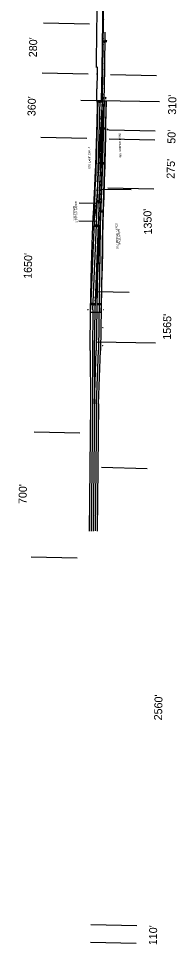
# Model space of a CAD drawing. Extents: x 1651568 to 1653044, y 601329 to 611807.
# Drawn here: x 1652071 to 1652957, y 601329 to 606513 of the extents above; entities that cross this region are included whole.
import ezdxf

# ---------------------------------------------------------------- set-up
doc = ezdxf.new("R2010")
doc.units = 0
for name, color, linetype in [('CM_Corridor_Design', 7, 'Continuous'), ('Default', 7, 'Continuous'), ('DR_X_Storm_Sewer', 7, 'Continuous'), ('DT_X_Break_Line', 7, 'Continuous'), ('DT_X_Contour_Major', 7, 'Continuous'), ('DT_X_Void', 7, 'Continuous'), ('GE_P_Alignment_500_Cardinal_Points', 7, 'Continuous'), ('GE_P_Alignment_500_Distances', 7, 'Continuous'), ('MD_P_Intersection_MatchLine', 7, 'Continuous'), ('PF_P_Grade_Line', 7, 'Continuous'), ('PF_P_Grade_Line_LT', 7, 'Continuous'), ('PF_X_Ground_Line', 7, 'Continuous'), ('PF_X_Ground_Line_LT', 7, 'Continuous'), ('PF_X_Ground_Line_RT', 7, 'Continuous'), ('PV_P_EOP', 7, 'Continuous'), ('PV_X_EOP', 7, 'Continuous'), ('RW_X_Esmt_LA', 7, 'Continuous'), ('SC_Scratch3', 7, 'Continuous')]:
    doc.layers.add(name, color=color, linetype=linetype)

msp = doc.modelspace()

# ---------------------------------------------------------------- linework, layer by layer
at = {"layer": 'CM_Corridor_Design'}
for p, q in [((1652550.1, 606379.2), (1652548.4, 606382.6)), ((1652550.1, 606379.2), (1652550.3, 606391.1)), ((1652550.1, 606379.2), (1652551.9, 606382.6)), ((1652562.4, 606391.9), (1652560.6, 606388.5)), ((1652562.4, 606391.9), (1652562.3, 606380)), ((1652562.4, 606391.9), (1652564.1, 606388.5)), ((1652545.6, 606061.3), (1652544, 606064.7)), ((1652545.6, 606061.3), (1652545.8, 606073.2)), ((1652545.6, 606061.3), (1652547.4, 606064.7)), ((1652558.4, 606073.2), (1652556.6, 606069.8)), ((1652558.4, 606073.2), (1652558.2, 606061.3)), ((1652558.4, 606073.2), (1652560, 606069.8)), ((1652537.6, 605892.1), (1652536, 605895.6)), ((1652537.6, 605892.1), (1652538.2, 605904)), ((1652537.6, 605892.1), (1652539.5, 605895.4)), ((1652552.2, 605903.6), (1652550.5, 605900.2)), ((1652552.2, 605903.6), (1652552.1, 605891.7)), ((1652552.2, 605903.6), (1652553.9, 605900.2)), ((1652527.9, 605697.6), (1652526.3, 605701.1)), ((1652527.9, 605697.6), (1652528.4, 605709.5)), ((1652527.9, 605697.6), (1652529.7, 605700.9)), ((1652546.1, 605708.3), (1652544.3, 605704.9)), ((1652546.1, 605708.3), (1652545.9, 605696.4)), ((1652546.1, 605708.3), (1652547.8, 605704.9)), ((1652516.5, 605484.2), (1652515, 605487.6)), ((1652516.5, 605484.2), (1652517.1, 605496)), ((1652516.5, 605484.2), (1652518.4, 605487.4)), ((1652537.5, 605438.6), (1652535.8, 605435.2)), ((1652537.5, 605438.6), (1652537.4, 605426.7)), ((1652537.5, 605438.6), (1652539.2, 605435.2)), ((1652500.3, 605347.7), (1652498.7, 605351.2)), ((1652500.3, 605347.7), (1652500.8, 605359.6)), ((1652500.3, 605347.7), (1652502.1, 605351)), ((1652512.1, 605347.4), (1652510.5, 605350.9)), ((1652512.1, 605347.4), (1652512.7, 605359.3)), ((1652512.1, 605347.4), (1652514, 605350.7)), ((1652482.4, 604908.8), (1652480.8, 604912.2)), ((1652482.4, 604908.8), (1652483, 604920.6)), ((1652482.4, 604908.8), (1652484.3, 604912)), ((1652494.2, 604908.5), (1652492.7, 604911.9)), ((1652494.2, 604908.5), (1652494.8, 604920.3)), ((1652494.2, 604908.5), (1652496.1, 604911.8)), ((1652516.1, 604919.9), (1652514.4, 604916.6)), ((1652516.1, 604919.9), (1652516, 604908.1)), ((1652516.1, 604919.9), (1652517.8, 604916.5)), ((1652529.3, 604919.6), (1652527.5, 604916.3)), ((1652529.3, 604919.6), (1652529.2, 604907.8)), ((1652529.3, 604919.6), (1652531, 604916.2))]:
    msp.add_line(p, q, dxfattribs=at)
at = {"layer": 'Default'}
msp.add_lwpolyline([(1652561.2, 606051.4), (1652560.5, 605997.6), (1652559.3, 605931.6), (1652557.9, 605851.7), (1652556.6, 605787.9), (1652554.4, 605691), (1652551.8, 605605.9), (1652548.6, 605514.1), (1652546.2, 605440.2), (1652544.1, 605364.6), (1652542.4, 605296.2), (1652540.8, 605209.6), (1652539.5, 605125.1), (1652535.9, 605025.9), (1652533.7, 604920.6), (1652533, 604867.1), (1652473.9, 604867.3), (1652474, 604883.4), (1652477.2, 604953.6), (1652478.6, 605051.2), (1652480.5, 605126.3), (1652482.2, 605188.7), (1652484.4, 605251.8), (1652485.9, 605296.5), (1652488.1, 605354.7), (1652489.8, 605399), (1652492.5, 605450.4), (1652495.1, 605500.8), (1652498.7, 605571.5), (1652501.1, 605625.4), (1652503.6, 605690.8), (1652506, 605754), (1652508, 605815.7), (1652509.8, 605869.3), (1652511.8, 605944.5), (1652513.2, 606013), (1652513.7, 606052.2)], close=True, dxfattribs=at)
at = {"layer": 'DR_X_Storm_Sewer'}
msp.add_lwpolyline([(1652536.1, 605556.8), (1652529.3, 605358.1), (1652526.8, 605192.9), (1652523.5, 604981.8)], dxfattribs=at)
at = {"layer": 'DT_X_Break_Line'}
for centre, radius in [((1652545.5, 606471.7), 1), ((1652546, 606506.7), 1), ((1652545.1, 606436.7), 1), ((1652544.3, 606366.7), 1), ((1652544.7, 606401.7), 1), ((1652543.8, 606331.7), 1), ((1652543, 606261.7), 1), ((1652543.4, 606296.7), 1), ((1652542.6, 606226.7), 1), ((1652541.4, 606156.7), 1), ((1652542, 606191.7), 1), ((1652540.8, 606121.7), 1), ((1652539.6, 606051.7), 1), ((1652540.2, 606086.7), 1), ((1652536.9, 606001.8), 1), ((1652533.2, 605951.8), 2), ((1652530.5, 605901.9), 2), ((1652545, 605901.5), 2), ((1652527.8, 605851.9), 2), ((1652542.8, 605851.6), 2), ((1652525.1, 605801.9), 2), ((1652540.9, 605801.6), 2), ((1652522.4, 605752), 2), ((1652538.8, 605751.6), 2), ((1652519.7, 605702), 2), ((1652535.3, 605701.7), 2), ((1652538.3, 605701.6), 2), ((1652517, 605652.1), 2), ((1652532.9, 605651.7), 2), ((1652536.7, 605651.6), 2), ((1652514.3, 605602.1), 2), ((1652530.5, 605601.7), 2), ((1652535, 605601.6), 2), ((1652511.6, 605552.1), 2), ((1652528, 605551.8), 2), ((1652533.6, 605551.6), 2), ((1652507.5, 605478.1), 2), ((1652508.9, 605502.2), 2), ((1652525.5, 605501.8), 2), ((1652531.4, 605501.7), 2), ((1652502.2, 605442.7), 2), ((1652505.2, 605462.4), 2), ((1652529.3, 605451.7), 2), ((1652495.9, 605403.2), 2), ((1652499.1, 605423), 2), ((1652527.2, 605401.7), 2), ((1652525.1, 605351.7), 2), ((1652523.1, 605301.8), 2), ((1652521, 605251.8), 2), ((1652518.9, 605201.8), 2), ((1652516.8, 605151.9), 2), ((1652514.7, 605101.9), 2), ((1652512.7, 605051.9), 2), ((1652506.8, 604969), 2), ((1652510.1, 604983.6), 2), ((1652510.6, 605001.9), 2), ((1652502.9, 604952.8), 2)]:
    msp.add_circle(centre, radius, dxfattribs=at)
at = {"layer": 'DT_X_Contour_Major'}
for p, q in [((1652540, 606229.1), (1652551.8, 607199.3)), ((1652507.5, 606238.7), (1652510.6, 606459.9)), ((1652514.1, 606240.6), (1652507.5, 606238.7)), ((1652513.5, 606206.6), (1652514.1, 606240.6)), ((1652513.5, 606197.5), (1652513.5, 606206.6)), ((1652537, 606051.8), (1652540, 606229.1)), ((1652509.9, 606079.3), (1652510.5, 606120.3)), ((1652510.5, 606120.3), (1652512.5, 606121.2)), ((1652509.5, 606053.1), (1652509.9, 606079.3)), ((1652509.5, 606052.3), (1652509.5, 606053.1)), ((1652513.7, 606052.2), (1652537, 606051.8))]:
    msp.add_line(p, q, dxfattribs=at)
for points in [[(1652551.8, 607199.3), (1652540, 606229.1), (1652537, 606051.8), (1652509.5, 606052.3), (1652509.9, 606079.3), (1652510.5, 606120.3), (1652512.5, 606121.2), (1652512.7, 606131.8), (1652513.5, 606197.5), (1652513.5, 606206.6), (1652514.1, 606240.6), (1652507.5, 606238.7), (1652510.6, 606459.8), (1652510.6, 606459.9), (1652511.3, 606521.8)], [(1652551.8, 607199.3), (1652540, 606229.1), (1652537, 606051.8), (1652509.5, 606052.3), (1652509.9, 606079.3), (1652510.5, 606120.3), (1652512.5, 606121.2), (1652512.7, 606131.8), (1652513.5, 606197.5), (1652513.5, 606206.6), (1652514.1, 606240.6), (1652507.5, 606238.7), (1652510.6, 606459.8), (1652510.6, 606459.9), (1652511.3, 606521.8)], [(1652510.6, 606459.8), (1652511.3, 606521.8), (1652511.5, 606531.9), (1652513, 606640.4), (1652508.6, 606640.4), (1652508.7, 606654.8), (1652513.2, 606654.8), (1652514.1, 606733)], [(1652512.5, 606121.2), (1652512.7, 606131.8), (1652513.5, 606197.5)]]:
    msp.add_lwpolyline(points, dxfattribs=at)
at = {"layer": 'DT_X_Void'}
for p, q in [((1652511.3, 606046.6), (1652521.3, 606046.5)), ((1652511.4, 606048.6), (1652521.4, 606048.5)), ((1652518.3, 606045), (1652514.3, 606045)), ((1652515.3, 606046.5), (1652515.3, 606045)), ((1652516.4, 606047.5), (1652516.4, 606047.5)), ((1652517.3, 606046.5), (1652517.3, 606045)), ((1652524.2, 606048.5), (1652534.2, 606048.4)), ((1652524.2, 606046.5), (1652534.2, 606046.4)), ((1652531.2, 606044.9), (1652527.2, 606045)), ((1652528.2, 606046.5), (1652528.2, 606045)), ((1652529.2, 606047.4), (1652529.2, 606047.4)), ((1652530.2, 606046.4), (1652530.2, 606044.9))]:
    msp.add_line(p, q, dxfattribs=at)
for points in [[(1652510.4, 606050.6), (1652510.3, 606044.6), (1652511.3, 606044.6), (1652511.4, 606050.6)], [(1652522.4, 606050.4), (1652522.3, 606044.4), (1652521.3, 606044.5), (1652521.4, 606050.5)], [(1652523.3, 606050.5), (1652523.2, 606044.5), (1652524.2, 606044.5), (1652524.3, 606050.5)], [(1652535.3, 606050.4), (1652535.2, 606044.4), (1652534.2, 606044.4), (1652534.3, 606050.4)]]:
    msp.add_lwpolyline(points, close=True, dxfattribs=at)
at = {"layer": 'GE_P_Alignment_500_Cardinal_Points'}
for p, q in [((1652468.2, 606481.1), (1652210.8, 606487.1)), ((1652461.8, 606201.2), (1652204.3, 606207.2)), ((1652861.9, 606046.2), (1652421, 606053.8)), ((1652453.4, 605841.3), (1652195.9, 605847.3)), ((1652701.6, 605553.9), (1652536.1, 605556.8)), ((1652511.4, 605477.1), (1652411.2, 605478.9)), ((1652509.7, 605377.2), (1652409.5, 605378.9)), ((1652838.7, 604696.3), (1652507.8, 604702))]:
    msp.add_line(p, q, dxfattribs=at)
at = {"layer": 'GE_P_Alignment_500_Distances'}
msp.add_line((1652691.7, 604979), (1652512.3, 604982.1), dxfattribs=at)
at = {"layer": 'MD_P_Intersection_MatchLine'}
for p, q in [((1652510.8, 606204.9), (1652512, 606204.9)), ((1652511.2, 606206.1), (1652512, 606206.1))]:
    msp.add_line(p, q, dxfattribs=at)
msp.add_lwpolyline([(1652511.2, 606206.1), (1652509.6, 606200.1), (1652512, 606200.1)], dxfattribs=at)
msp.add_circle((1652510.3, 606202.9), 1.3, dxfattribs=at)
msp.add_arc((1652512, 606205.5), 0.638, 268.8767, 91.1233, dxfattribs=at)
at = {"layer": 'PF_P_Grade_Line'}
for p, q in [((1652515.5, 606052.6), (1652502, 605598.4)), ((1652562.5, 606051.2), (1652549, 605597)), ((1652549, 605597), (1652540.8, 605357.7)), ((1652494.1, 605377.4), (1652474, 604883.4)), ((1652540.8, 605357.7), (1652530, 604655.4)), ((1652473.4, 604654.8), (1652474, 604883.4)), ((1652473.4, 604654.8), (1652474.9, 604355.7)), ((1652519.9, 604356.4), (1652530, 604655.4)), ((1652474.9, 604355.7), (1652467.1, 603643.1)), ((1652519.9, 604356.4), (1652512.1, 603643.8))]:
    msp.add_line(p, q, dxfattribs=at)
msp.add_lwpolyline([(1652494.1, 605377.4), (1652502, 605598.4), (1652515.5, 606052.6)], dxfattribs=at)
at = {"layer": 'PF_P_Grade_Line_LT'}
for p, q in [((1652568.6, 605891.9), (1652568.7, 605892.8)), ((1652568.6, 605891.9), (1652574.6, 605890.2)), ((1652569.9, 605891.5), (1652569.9, 605892.7))]:
    msp.add_line(p, q, dxfattribs=at)
msp.add_circle((1652571.8, 605891), 1.3, dxfattribs=at)
msp.add_arc((1652569.3, 605892.8), 0.638, 357.894, 180.1406, dxfattribs=at)
at = {"layer": 'PF_X_Ground_Line'}
for p, q in [((1652562.8, 605925), (1652559.6, 605925)), ((1652561.2, 605925), (1652561.3, 605926.6)), ((1652561.2, 605925), (1652561.2, 605925)), ((1652458.5, 604883.5), (1652461.7, 604883.4)), ((1652460.1, 604883.5), (1652460, 604881.9)), ((1652460.1, 604883.5), (1652460.1, 604883.5)), ((1652547.7, 604881.4), (1652544.5, 604881.5)), ((1652546.1, 604881.5), (1652546.1, 604883.1)), ((1652546.1, 604881.5), (1652546.1, 604881.5)), ((1652546, 604781.5), (1652542.8, 604781.5)), ((1652544.4, 604781.5), (1652544.4, 604783.1)), ((1652544.4, 604781.5), (1652544.4, 604781.5)), ((1652544.3, 604681.5), (1652541.1, 604681.5)), ((1652542.7, 604681.5), (1652542.7, 604683.1)), ((1652542.7, 604681.5), (1652542.7, 604681.5))]:
    msp.add_line(p, q, dxfattribs=at)
at = {"layer": 'PF_X_Ground_Line_LT'}
for p, q in [((1652539.5, 606051.9), (1652526, 605597.7)), ((1652526, 605597.7), (1652517.8, 605358.4)), ((1652517.3, 605358.4), (1652497.9, 604882.4)), ((1652518.3, 605358.4), (1652507, 604654.3)), ((1652497.9, 604882.4), (1652495.4, 604654.4)), ((1652495.4, 604654.4), (1652496.4, 604355.3)), ((1652497.4, 604355.3), (1652507, 604654.3)), ((1652496.9, 604355.3), (1652489.1, 603642.7))]:
    msp.add_line(p, q, dxfattribs=at)
at = {"layer": 'PF_X_Ground_Line_RT'}
for p, q in [((1652527.5, 606052.2), (1652514, 605598)), ((1652551, 606051.5), (1652537.5, 605597.3)), ((1652514, 605598.1), (1652505.8, 605358.8)), ((1652537.5, 605597.3), (1652529.3, 605358.1)), ((1652505.3, 605358.9), (1652485.9, 604882.9)), ((1652529.3, 605358.1), (1652518.5, 604655.6)), ((1652487.4, 604882.7), (1652484.9, 604654.5)), ((1652484.9, 604654.5), (1652486.4, 604355.4)), ((1652508.4, 604356.6), (1652518.5, 604655.6)), ((1652486.4, 604355.4), (1652478.6, 603642.8)), ((1652508.4, 604356.6), (1652500.6, 603644))]:
    msp.add_line(p, q, dxfattribs=at)
at = {"layer": 'PV_P_EOP'}
for p, q in [((1652544, 606229), (1652555.8, 607199.3)), ((1652541, 606051.7), (1652544, 606229)), ((1652509.9, 605477.1), (1652541, 606051.7)), ((1652494.3, 605377.4), (1652509.9, 605477.1))]:
    msp.add_line(p, q, dxfattribs=at)
at = {"layer": 'PV_X_EOP'}
for p, q in [((1652554, 606228.9), (1652556.5, 606437.4)), ((1652551, 606051.5), (1652554, 606228.8))]:
    msp.add_line(p, q, dxfattribs=at)
at = {"layer": 'RW_X_Esmt_LA'}
for p, q in [((1652521.9, 605476.9), (1652550.5, 606051.6)), ((1652536.1, 605556.8), (1652551.5, 606051.5)), ((1652512.3, 604982.1), (1652536.1, 605556.8)), ((1652500, 604932.5), (1652512.3, 604982.1))]:
    msp.add_line(p, q, dxfattribs=at)
at = {"layer": 'SC_Scratch3'}
for p, q in [((1652844, 606192.3), (1652586.6, 606198.3)), ((1652836.8, 605882.4), (1652579.4, 605888.4)), ((1652835.7, 605832.4), (1652578.2, 605838.4)), ((1652829.3, 605557.5), (1652571.8, 605563.5)), ((1652415.2, 604191.7), (1652157.7, 604197.7)), ((1652793, 603992.9), (1652535.6, 603998.9)), ((1652399, 603491.9), (1652141.5, 603497.9)), ((1652733.7, 601433.6), (1652476.2, 601439.6)), ((1652731.4, 601333.6), (1652473.9, 601339.6))]:
    msp.add_line(p, q, dxfattribs=at)

# ---------------------------------------------------------------- texts
at = {"layer": 'GE_P_Alignment_500_Cardinal_Points'}
for s, height, rotation, p in [("280'", 44.8, 88.672, (1652173.4, 606296.1)), ("360'", 44.8, 88.672, (1652165.7, 605965.9)), ("495' BUFFER (MIN)", 11.2, 91.5443, (1652647.1, 605733)), ("575' LANE SHIFT", 11.2, 91.5443, (1652475.7, 605671.9)), ('STREAM TAPER', 11.2, 91.5443, (1652402.1, 605371.1)), ("100' DOWN", 11.2, 91.5443, (1652389.2, 605382.9)), ("1350'", 44.8, 91.5443, (1652819.2, 605304.7)), ("575' MERGE TAPER", 11.2, 91.5443, (1652630.5, 605223)), ('50x11.5=575', 11.2, 91.5443, (1652642.5, 605245.3))]:
    msp.add_text(s, height=height, rotation=rotation, dxfattribs=at).set_placement(p)
at = {"layer": 'SC_Scratch3'}
for s, p in [("310'", (1652953.9, 605974.5)), ("50'", (1652950.2, 605811.9)), ("275'", (1652945.6, 605615.5)), ("1650'", (1652144.6, 605055.2)), ("1565'", (1652924.7, 604714.4)), ("700'", (1652115.4, 603794.4)), ("2560'", (1652875.3, 602583.3)), ("110'", (1652846.1, 601324.4))]:
    msp.add_text(s, height=44.8, rotation=88.672, dxfattribs=at).set_placement(p)

doc.saveas('drawing.dxf')
